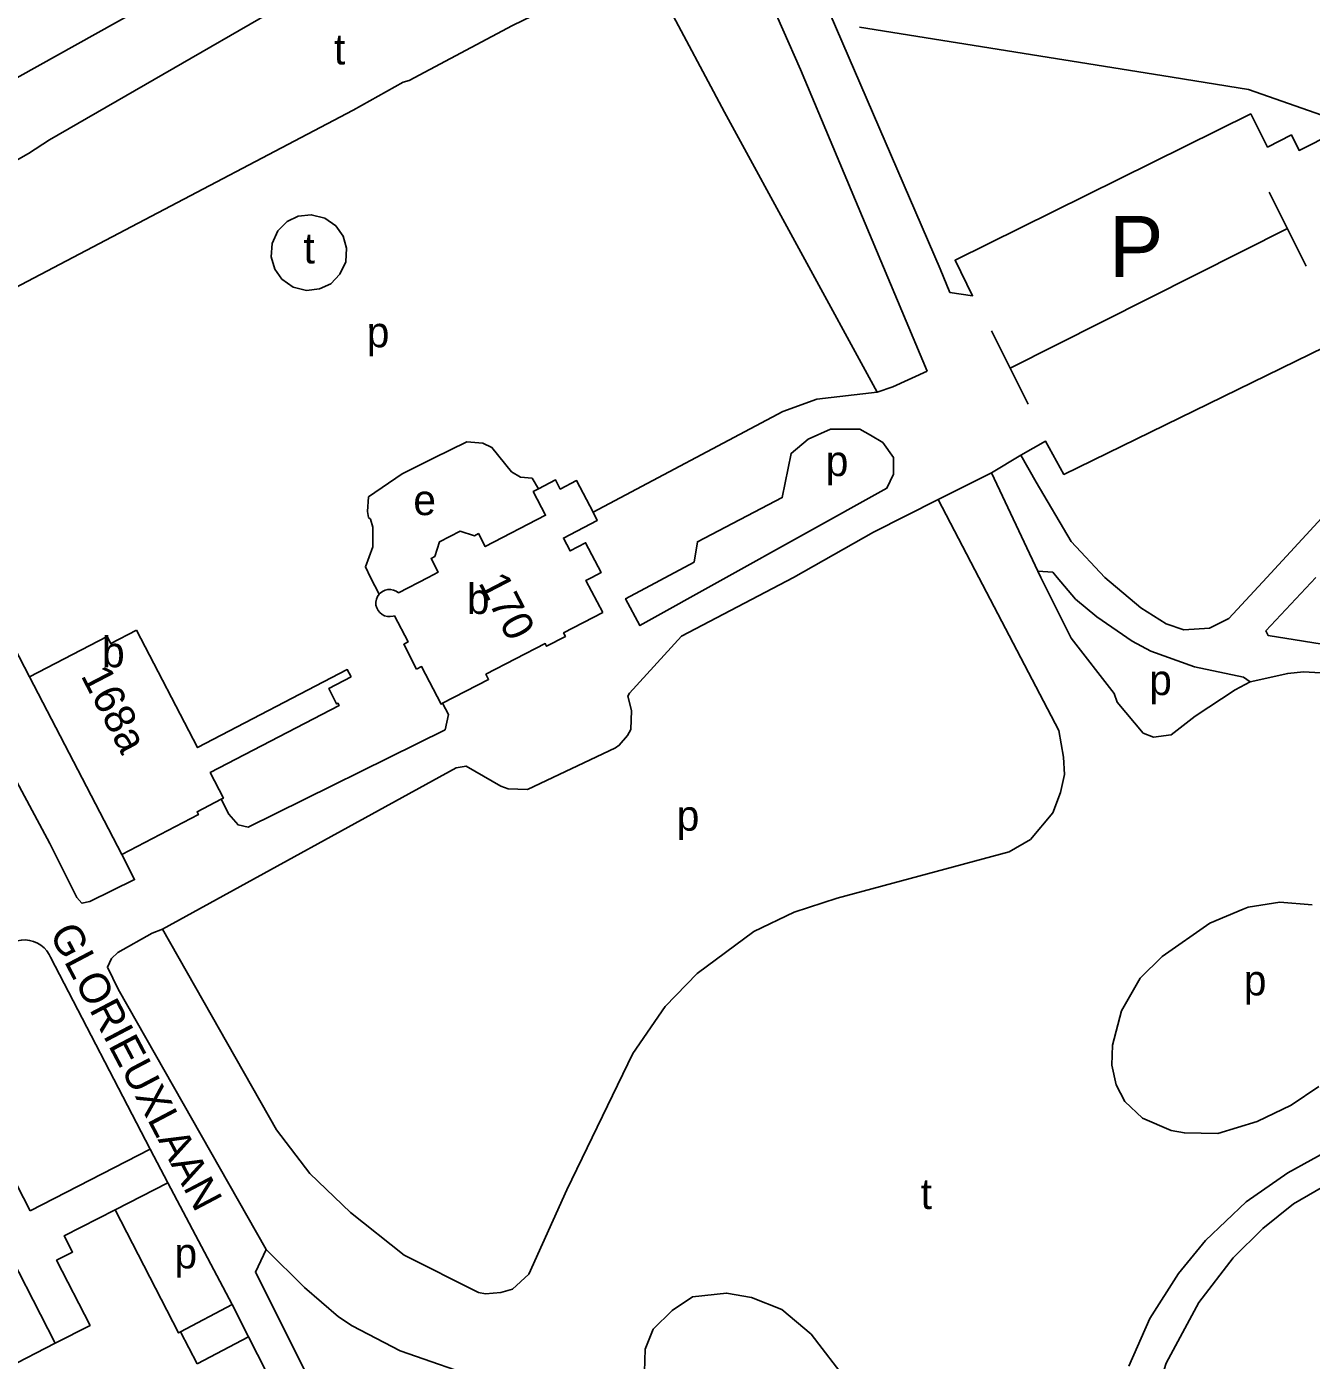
# Model space of a CAD drawing. Extents: x 161141 to 163125, y 381621 to 383200.
# Drawn here: x 162648.6 to 162817.4, y 382330.5 to 382505.7 of the extents above; entities that cross this region are included whole.
import ezdxf

# ---------------------------------------------------------------- set-up
doc = ezdxf.new("R2010")
doc.units = 0
for name, color, linetype in [('BLT_Basislijn', 7, 'Continuous'), ('BLT_Bebouwing', 7, 'Continuous'), ('BLT_Centroide', 7, 'Continuous'), ('BLT_Huisnummer', 7, 'Continuous'), ('BLT_Straatnaam_verkleind', 7, 'Continuous'), ('BLT_Tekst_parkeren', 7, 'Continuous')]:
    doc.layers.add(name, color=color, linetype=linetype)

msp = doc.modelspace()

# ---------------------------------------------------------------- linework, layer by layer
at = {"layer": 'BLT_Basislijn'}
for p, q in [((162732.47, 382509.17), (162740.29, 382494.42)), ((162740.29, 382494.42), (162760.34, 382457.65)), ((162811.87, 382483.93), (162816.73, 382474.21)), ((162814.26, 382479.15), (162777.82, 382460.81)), ((162775.38, 382465.7), (162780.18, 382456.09)), ((162752.44, 382456.74), (162760.34, 382457.65)), ((162697.96, 382446.95), (162702.06, 382448.98)), ((162779.21, 382449.4), (162775.35, 382447.05)), ((162768.38, 382443.58), (162775.35, 382447.05)), ((162775.35, 382447.05), (162781.44, 382434.13)), ((162641.52, 382364.8), (162649.05, 382350.14)), ((162639.36, 382358.07), (162652.36, 382332.73)), ((162664.83, 382358.24), (162667.16, 382353.82)), ((162667.16, 382353.82), (162675.6, 382337.8)), ((162668.83, 382334.24), (162675.6, 382337.8)), ((162671.01, 382330.01), (162677.76, 382333.57)), ((162677.76, 382333.57), (162684.47, 382320.45))]:
    msp.add_line(p, q, dxfattribs=at)
for points in [[(162635.09, 382492.15), (162665.21, 382508.92), (162681.25, 382517.73), (162685.54, 382519.91), (162688.83, 382522.06), (162701.71, 382527.67), (162705.61, 382529.13), (162714.9, 382532), (162715.61, 382533.53)], [(162717.74, 382525.73), (162713.53, 382524.85), (162711.3, 382524.13), (162704.33, 382521.18), (162697.44, 382517.47), (162696.59, 382516.78), (162651.61, 382490.8), (162648.85, 382489.01), (162625.07, 382475.48), (162622.04, 382472.42), (162620.44, 382469.49), (162619.11, 382464.04), (162619.69, 382459.37), (162620.18, 382458.53)], [(162769.9, 382470.76), (162768.63, 382473.86), (162746.13, 382525.99)], [(162732.47, 382509.17), (162732.08, 382509.61), (162731.19, 382511.7), (162726.24, 382512.22), (162724.24, 382511.84), (162718.98, 382508.96), (162712.44, 382505.83), (162698.84, 382498.61), (162698.08, 382498.37), (162691.49, 382494.7), (162628.15, 382461.41), (162628.26, 382460.6), (162629.1, 382458.51), (162642.19, 382433.33), (162648.99, 382420.26)], [(162745.62, 382510.59), (162750.26, 382500.06), (162766.91, 382460.44)], [(162758.04, 382505.62), (162797.77, 382499.25), (162809.14, 382497.43), (162833.81, 382488.81), (162849.22, 382481.1)], [(162769.9, 382470.76), (162772.89, 382470.32), (162770.58, 382474.98), (162809.44, 382494.21), (162811.64, 382489.86), (162814.78, 382491.45), (162815.79, 382489.42), (162820.4, 382491.71), (162829.01, 382474.29), (162824.42, 382472.01), (162826.75, 382467.3), (162784.89, 382446.86), (162782.47, 382451.21), (162779.21, 382449.4)], [(162681.2, 382473.83), (162680.74, 382475.42), (162680.85, 382477.2), (162681.61, 382478.86), (162682.83, 382480.08), (162684.28, 382480.78), (162686, 382480.97), (162687.76, 382480.53), (162689.22, 382479.51), (162690.18, 382478.16)], [(162690.18, 382478.16), (162690.64, 382476.57), (162690.52, 382474.79), (162689.77, 382473.14), (162688.55, 382471.91), (162687.1, 382471.22), (162685.38, 382471.02), (162683.62, 382471.46), (162682.15, 382472.49), (162681.2, 382473.83)], [(162842.28, 382466.36), (162832.7, 382456.24), (162811.53, 382433.33), (162806.55, 382427.92), (162804, 382426.67), (162800.65, 382426.43), (162798.32, 382427.22), (162794.98, 382429.33), (162790.27, 382433.33), (162785.83, 382438.06), (162781.22, 382445.84), (162779.21, 382449.4)], [(162760.34, 382457.65), (162762.4, 382458.35), (162766.91, 382460.44)], [(162661.12, 382396.95), (162662.78, 382393.63), (162656.89, 382390.76), (162655.87, 382390.53), (162655.2, 382391.27), (162651.63, 382398.37), (162634.55, 382430.21), (162633.05, 382433.33), (162629.89, 382439.91), (162620.71, 382457.03), (162620.18, 382458.53)], [(162752.44, 382456.74), (162747.94, 382455.14), (162723.03, 382441.88)], [(162715.86, 382444.98), (162715, 382446.35), (162713.47, 382446.51), (162712.29, 382447.2), (162709.74, 382450.4), (162708.53, 382450.97), (162706.45, 382451.13), (162702.06, 382448.98)], [(162697.96, 382446.95), (162693.54, 382443.89), (162693.39, 382441.97), (162693.51, 382441.2), (162693.77, 382440.96), (162694.07, 382439.94), (162694.1, 382437.35), (162693.11, 382434.71), (162693.8, 382433.33), (162694.9, 382431.11)], [(162666.45, 382387.13), (162705.05, 382408.31), (162706.35, 382408.54), (162710.92, 382405.92), (162711.87, 382405.55), (162714.42, 382405.47), (162725.98, 382410.96), (162726.47, 382411.28), (162727.56, 382412.57), (162727.97, 382413.36), (162728.08, 382415.84), (162727.59, 382417.72), (162727.81, 382418.14), (162734.62, 382425.63), (162749.34, 382433.33), (162759.87, 382439.25), (162768.38, 382443.58)], [(162666.45, 382387.13), (162681.43, 382360.76), (162685.83, 382355.02), (162691.15, 382349.92), (162698.2, 382344.3), (162707.95, 382339.4), (162708.91, 382339.24), (162710.91, 382339.4), (162712.45, 382339.82), (162714.58, 382341.79), (162719.57, 382352.89), (162728.24, 382370.77), (162732.5, 382376.95), (162736.69, 382381.29), (162744.13, 382386.83), (162749.43, 382389.37), (162755.11, 382391.2), (162777.7, 382397.29), (162780.51, 382398.92), (162783.44, 382402.42), (162784.43, 382405.06), (162784.95, 382407.43), (162784.81, 382409.72), (162784.23, 382413.2), (162773.72, 382433.33), (162768.38, 382443.58)], [(162781.44, 382434.13), (162783.41, 382434.03), (162784, 382433.33), (162786.42, 382430.49), (162789.2, 382428.15), (162793.86, 382424.96), (162796.3, 382423.62), (162802.03, 382421.6), (162808.47, 382420.21), (162809.37, 382419.62)], [(162781.44, 382434.13), (162781.84, 382433.33), (162785.83, 382425.35), (162791.5, 382418.07), (162791.89, 382416.93), (162795.3, 382412.88), (162796.67, 382412.32), (162798.96, 382412.67), (162802.12, 382415.1), (162807.4, 382418.58), (162809.37, 382419.62)], [(162817.97, 382433.33), (162811.43, 382426.33), (162811.74, 382425.68), (162824.53, 382423.64)], [(162793.43, 382329.7), (162796.19, 382335.99), (162799.92, 382341.89), (162803.47, 382346.22), (162808.84, 382351.29), (162814.29, 382355.12), (162826.41, 382361.78), (162830.68, 382364.96), (162837.15, 382371.12), (162842.58, 382377.55), (162845.92, 382382.69), (162847.91, 382388.81), (162848.15, 382395.11), (162847.51, 382399.65), (162846.4, 382403), (162843.53, 382408.02), (162839.68, 382412.25), (162834.7, 382415.59), (162827.59, 382418.54), (162821.47, 382420.37), (162820.03, 382420.69), (162816.34, 382420.93), (162814.29, 382420.71), (162809.37, 382419.62)], [(162674.14, 382404.18), (162675.17, 382402.24), (162676.39, 382400.82), (162677.71, 382400.53), (162703.58, 382413.31), (162704.04, 382415.31), (162703.25, 382416.79)], [(162817.48, 382390.33), (162813.24, 382390.65), (162809.1, 382390.01), (162808.45, 382389.74)], [(162808.45, 382389.74), (162804.06, 382387.92), (162797.78, 382383.55), (162794.91, 382380.68), (162792.47, 382376.4), (162791.25, 382371.88), (162791.16, 382369.26), (162791.73, 382366.66), (162792.9, 382364.49), (162795.23, 382362.29), (162798.96, 382360.68), (162800.71, 382360.36), (162805.11, 382360.28), (162810.28, 382361.87), (162814.74, 382364.02), (162818.38, 382366.45)], [(162666.45, 382387.13), (162665.08, 382386.58), (162660.58, 382384.07), (162659.75, 382383.26), (162659.22, 382382.15), (162660.63, 382379.23), (162680.09, 382345.06)], [(162646.38, 382385.15), (162646.86, 382385.4), (162647.37, 382385.58), (162647.91, 382385.68), (162648.45, 382385.7), (162648.99, 382385.64), (162649.51, 382385.51), (162650.01, 382385.29), (162650.48, 382385.01), (162650.89, 382384.66), (162651.25, 382384.26), (162651.55, 382383.8), (162651.73, 382383.43)], [(162651.73, 382383.43), (162664.83, 382358.24)], [(162795.31, 382318.92), (162796.55, 382324.54), (162798.32, 382330.09), (162802.6, 382338.08), (162807.1, 382343.95), (162811.01, 382347.79), (162815.06, 382351.04), (162832.69, 382361.24), (162833.33, 382361.51), (162835.49, 382361.72), (162838.89, 382358.34), (162846.23, 382351.61)], [(162649.05, 382350.14), (162664.83, 382358.24)], [(162660.24, 382350.27), (162667.16, 382353.82)], [(162680.09, 382345.06), (162678.66, 382342.05), (162686.04, 382327.38)], [(162755.3, 382297.03), (162743.27, 382303.32), (162734.92, 382309.54), (162730.32, 382313.28), (162727.37, 382315.33), (162722.33, 382319.41), (162713.88, 382325.38), (162709, 382327.77), (162697.69, 382331.75), (162691.38, 382335), (162689.56, 382336.21), (162685.12, 382340.05), (162680.09, 382345.06)], [(162675.6, 382337.8), (162677.76, 382333.57)], [(162743.82, 382338.74), (162740.56, 382339.32), (162736.1, 382338.81), (162733.4, 382337.04), (162730.9, 382334.56), (162729.88, 382331.93), (162729.8, 382328.96), (162730.59, 382326.71), (162741.28, 382315.77), (162743.71, 382313.63), (162745.34, 382312.37), (162748.53, 382311.83), (162749.65, 382311.99), (162752.24, 382313.2), (162754.91, 382315.64), (162756.69, 382317.93), (162757.53, 382320.23), (162757.78, 382322.83), (162757.23, 382325.95), (162756.44, 382327.7), (162751.66, 382333.92), (162747.83, 382337.17), (162743.82, 382338.74)]]:
    msp.add_lwpolyline(points, dxfattribs=at)
msp.add_lwpolyline([(162758.05, 382452.8), (162754.23, 382452.8), (162751.3, 382451.47), (162749.04, 382449.62), (162747.88, 382443.82), (162736.74, 382438.02), (162736.31, 382435.35), (162727.29, 382430.53), (162729.17, 382427.01), (162761.62, 382445.05), (162762.48, 382446.89), (162762.48, 382449.09), (162761.1, 382451.04), (162759.46, 382452.03)], close=True, dxfattribs=at)
at = {"layer": 'BLT_Bebouwing'}
msp.add_line((162661.12, 382396.95), (162648.99, 382420.26), dxfattribs=at)
for points in [[(162697.46, 382431.3), (162701.36, 382433.33), (162702.68, 382434.02), (162701.74, 382435.82), (162702.24, 382436.08), (162702.85, 382438.01), (162705.55, 382439.41), (162707.45, 382438.81), (162707.96, 382439.08), (162708.85, 382437.37), (162716.79, 382441.5), (162715.17, 382444.61), (162715.86, 382444.98)], [(162715.86, 382444.98), (162718.09, 382446.13), (162718.71, 382444.93), (162720.86, 382446.05), (162723.03, 382441.88)], [(162723.03, 382441.88), (162723.58, 382440.82), (162719.12, 382438.49), (162720, 382436.8), (162722.05, 382437.87), (162724.08, 382433.97), (162722.85, 382433.33), (162722.09, 382432.93), (162724.29, 382428.71)], [(162694.9, 382431.11), (162694.69, 382430.8), (162694.55, 382430.45), (162694.49, 382430.07), (162694.5, 382429.7), (162694.6, 382429.33), (162694.77, 382428.99), (162695.01, 382428.7), (162695.3, 382428.46), (162695.64, 382428.29), (162696, 382428.2), (162696.38, 382428.18), (162696.75, 382428.24), (162696.93, 382428.3)], [(162697.46, 382431.3), (162697.15, 382431.52), (162696.8, 382431.67), (162696.43, 382431.74), (162696.05, 382431.74), (162695.69, 382431.65), (162695.34, 382431.49), (162695.04, 382431.26), (162694.9, 382431.11)], [(162699.82, 382421.26), (162698.15, 382424.54), (162698.73, 382424.85), (162696.93, 382428.3)], [(162724.29, 382428.71), (162719.15, 382426.04), (162719.39, 382425.57), (162716.92, 382424.28), (162716.73, 382424.64), (162708.95, 382420.6), (162709.3, 382419.93), (162703.25, 382416.79)], [(162648.99, 382420.26), (162659.18, 382425.56), (162659.66, 382424.64), (162663.03, 382426.4)], [(162663.03, 382426.4), (162671.06, 382410.98), (162690.73, 382421.22), (162691.23, 382420.26)], [(162691.23, 382420.26), (162688.31, 382418.74), (162689.33, 382416.71), (162689.49, 382416.79), (162689.65, 382416.49), (162672.72, 382407.68), (162674.46, 382404.34), (162674.14, 382404.18)], [(162703.25, 382416.79), (162703.06, 382416.69), (162700.49, 382421.61), (162699.82, 382421.26)], [(162674.14, 382404.18), (162670.99, 382402.54), (162671.18, 382402.18), (162661.12, 382396.95)], [(162652.36, 382332.73), (162656.94, 382335.08), (162652.53, 382343.63), (162654.64, 382344.7), (162653.53, 382346.83), (162660.24, 382350.27)], [(162660.24, 382350.27), (162668.56, 382334.08), (162668.83, 382334.24)], [(162593.61, 382334.6), (162611.46, 382312.68), (162612.67, 382311.2), (162618.88, 382314.39), (162618.29, 382315.57), (162618.57, 382315.71), (162618.72, 382315.43), (162635.87, 382324.25), (162636.39, 382323.24), (162640.3, 382325.25), (162639.78, 382326.26), (162652.36, 382332.73)], [(162668.83, 382334.24), (162671.01, 382330.01)]]:
    msp.add_lwpolyline(points, dxfattribs=at)

# ---------------------------------------------------------------- texts
at = {"layer": 'BLT_Centroide'}
for s, p in [('t', (162688.98, 382500.71)), ('t', (162684.98, 382474.57)), ('p', (162693.29, 382463.56)), ('p', (162753.59, 382446.64)), ('e', (162699.41, 382441.51)), ('b', (162706.45, 382428.53)), ('b', (162658.51, 382421.53)), ('p', (162796.09, 382417.87)), ('p', (162734.01, 382400.06)), ('p', (162808.52, 382378.42)), ('t', (162766.06, 382350.36)), ('p', (162668.03, 382342.56))]:
    msp.add_text(s, height=4, dxfattribs=at).set_placement(p)
at = {"layer": 'BLT_Huisnummer'}
for s, p in [('170', (162707.9, 382432.64)), ('168a', (162655.66, 382420.43))]:
    msp.add_text(s, height=4, rotation=297.4414, dxfattribs=at).set_placement(p)
at = {"layer": 'BLT_Straatnaam_verkleind'}
msp.add_text('GLORIEUXLAAN', height=4, rotation=297.7739, dxfattribs=at).set_placement((162651.52, 382386.59))
at = {"layer": 'BLT_Tekst_parkeren'}
msp.add_text('P', height=8, dxfattribs=at).set_placement((162790.82, 382472.8))

doc.saveas('drawing.dxf')
